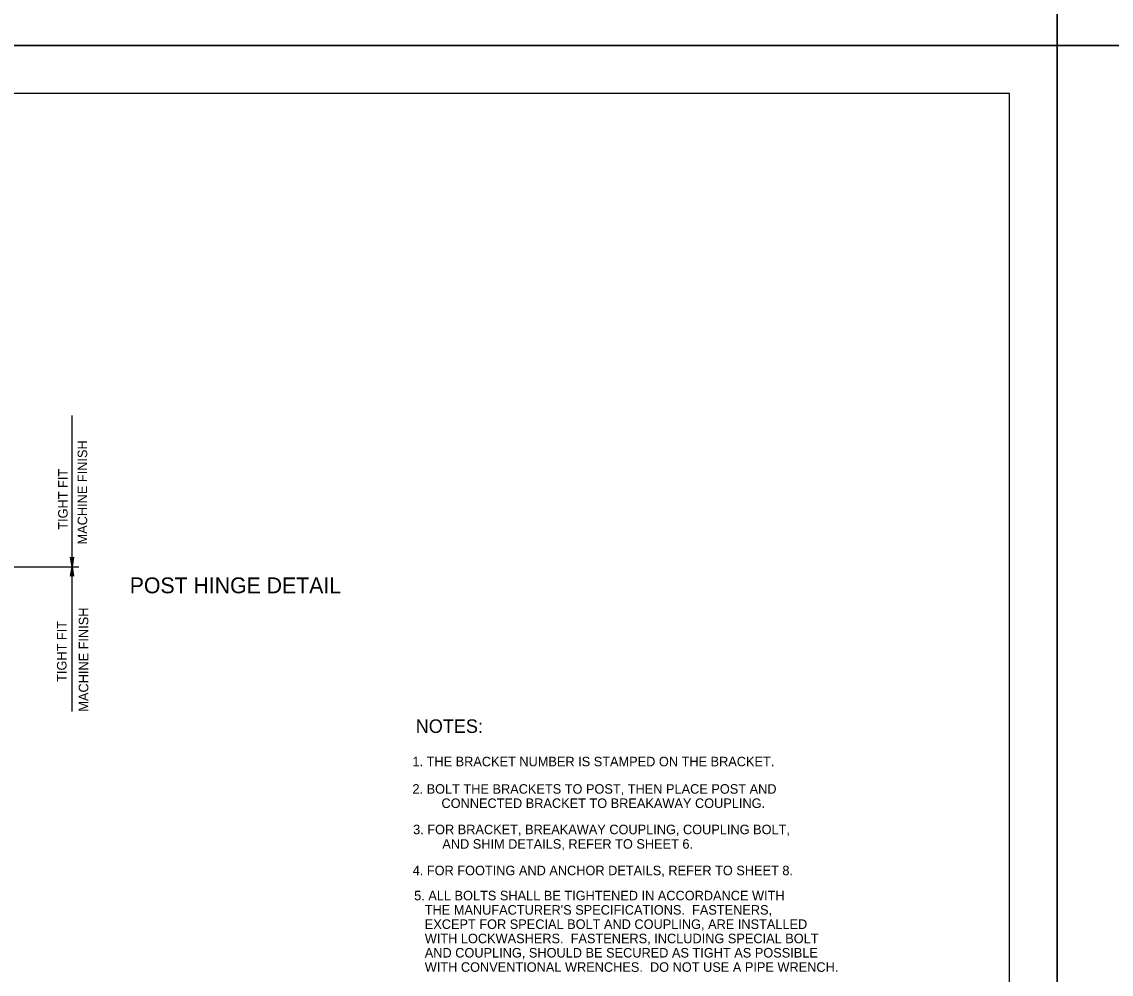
# Model space of a CAD drawing. Extents: x 637580 to 641008, y 294594 to 295782.
# Drawn here: x 638095.4 to 638438.3, y 294895.4 to 295195.1 of the extents above; entities that cross this region are included whole.
import ezdxf

# ---------------------------------------------------------------- set-up
doc = ezdxf.new("R2010")
doc.units = 0
for name, color, linetype in [('1', 7, 'Continuous'), ('2', 7, 'Continuous'), ('3', 7, 'Continuous'), ('PLT-BNDY', 7, 'Continuous')]:
    doc.layers.add(name, color=color, linetype=linetype)

# ---------------------------------------------------------------- blocks, each defined once
blk = doc.blocks.new('RARROW')
at = {"layer": '3'}
blk.add_lwpolyline([(-2.2695, 0.285), (-2.184875, 0.12075), (0, 0), (-2.2695, 0.285), (-2.38575, 0.384625), (0, 0), (-2.183125, -0.108), (-2.262875, -0.2705), (0, 0), (-2.38575, -0.379125), (-2.262875, -0.2705)], dxfattribs=at)

msp = doc.modelspace()

# ---------------------------------------------------------------- linework, layer by layer
at = {"layer": '1'}
for p in [(637620.31, 295172.63), (638406.31, 294608.63)]:
    msp.add_line(p, (638406.31, 295172.63), dxfattribs=at)
at = {"layer": '2'}
for p, q in [((638111.27, 295023.63), (638111.27, 295071.26)), ((638040.68, 295023.63), (638113.4, 295023.63)), ((638111.27, 294978.01), (638111.27, 295023.63))]:
    msp.add_line(p, q, dxfattribs=at)
at = {"layer": 'PLT-BNDY'}
for points in [[(637580.31, 295781.63), (638421.31, 295781.63), (638421.31, 295187.63), (637580.31, 295187.63)], [(638421.31, 295781.63), (639262.31, 295781.63), (639262.31, 295187.63), (638421.31, 295187.63)], [(637580.31, 295187.63), (638421.31, 295187.63), (638421.31, 294593.63), (637580.31, 294593.63)], [(638421.31, 295187.63), (639262.31, 295187.63), (639262.31, 294593.63), (638421.31, 294593.63)]]:
    msp.add_lwpolyline(points, close=True, dxfattribs=at)

# ---------------------------------------------------------------- block references
at = {"layer": '2', "xscale": 1.2574347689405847, "yscale": 1.3092961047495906}
for rotation in [-90.00000000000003, 89.99999999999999]:
    msp.add_blockref('RARROW', (638111.27, 295023.63), dxfattribs=dict(at, rotation=rotation))

# ---------------------------------------------------------------- texts
at = {"layer": '1'}
for s, p in [('1. THE BRACKET NUMBER IS STAMPED ON THE BRACKET.', (638218.4, 294960.8)), ('2. BOLT THE BRACKETS TO POST, THEN PLACE POST AND ', (638218.41, 294952.17)), ('CONNECTED BRACKET TO BREAKAWAY COUPLING.', (638227.53, 294947.68)), ('3. FOR BRACKET, BREAKAWAY COUPLING, COUPLING BOLT, ', (638218.62, 294939.42)), ('AND SHIM DETAILS, REFER TO SHEET 6.', (638227.81, 294934.86)), ('4. FOR FOOTING AND ANCHOR DETAILS, REFER TO SHEET 8.', (638218.48, 294926.51)), ('5. ALL BOLTS SHALL BE TIGHTENED IN ACCORDANCE WITH', (638218.94, 294918.61)), ("   THE MANUFACTURER'S SPECIFICATIONS.  FASTENERS,", (638218.94, 294914.11)), ('   EXCEPT FOR SPECIAL BOLT AND COUPLING, ARE INSTALLED', (638218.94, 294909.61)), ('   WITH LOCKWASHERS.  FASTENERS, INCLUDING SPECIAL BOLT', (638218.94, 294905.11)), ('   AND COUPLING, SHOULD BE SECURED AS TIGHT AS POSSIBLE', (638218.94, 294900.61)), ('   WITH CONVENTIONAL WRENCHES.  DO NOT USE A PIPE WRENCH.', (638218.94, 294896.11))]:
    msp.add_text(s, height=3, dxfattribs=at).set_placement(p)
at = {"layer": '2'}
for s, height, p in [('POST HINGE DETAIL', 5, (638129.43, 295015.25)), ('NOTES:', 4.25, (638219.44, 294971.31))]:
    msp.add_text(s, height=height, dxfattribs=at).set_placement(p)
at = {"layer": '3'}
for s, p in [('MACHINE FINISH', (638116.02, 295030.63)), ('TIGHT FIT', (638109.89, 295035.25)), ('MACHINE FINISH', (638116.39, 294978)), ('TIGHT FIT', (638109.52, 294987.38))]:
    msp.add_text(s, height=3, rotation=90, dxfattribs=at).set_placement(p)

doc.saveas('drawing.dxf')
